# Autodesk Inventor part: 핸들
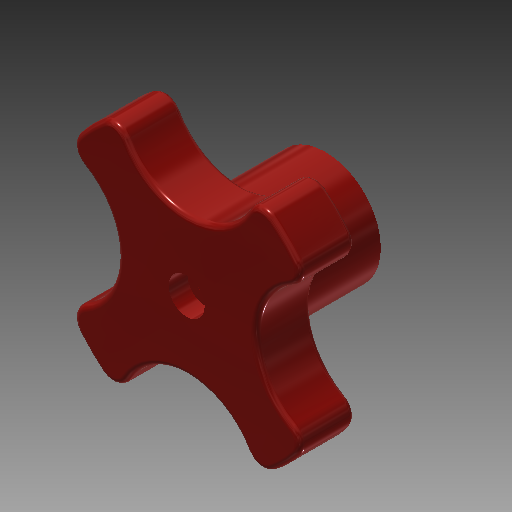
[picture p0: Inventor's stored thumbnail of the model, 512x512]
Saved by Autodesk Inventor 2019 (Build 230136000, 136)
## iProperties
Created: 2018-01
Part Number: 핸들
Material: ABS 플라스틱
Document SubType Name: Modeling
Designer: mduedu
Density: 1 g/cm^3
Appearance: 주황색-빨간색
Author: mduedu
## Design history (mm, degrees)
sketch "스케치1"
  geometry: C1 r 10 at (0, 0); C2 r 25 at (0, 0); 1 further point
  constraints: 2 centre point, 2 coincident
  dimensions: "d0" = 20 diameter of C1; "d1" = 50 diameter of C2
extrude "돌출1" new body sketch "스케치1" distance "d2" = 15; taper "d3" = 0 deg
extrude "돌출2" join sketch "스케치1" distance "d4" = 10; taper "d5" = 0 deg
sketch "스케치2" dims "d8" = 15
  geometry: L1 (-6, -6)-(-4.5, -6); L2 (6, -6)-(6, -4.5); L3 (6, 6)-(4.5, 6); L4 (-6, 6)-(-6, 4.5); L5 (-6, -6)-(6, 6); L6 (6, -6)-(-6, 6); L7 (-4.5, 6)-(-6, 6); L8 (4.5, 6)-(-4.5, 6); L9 (6, 4.5)-(6, 6); L10 (6, -4.5)-(6, 4.5); L11 (4.5, -6)-(6, -6); L12 (-4.5, -6)-(4.5, -6); L13 (-6, -4.5)-(-6, -6); L14 (-6, 4.5)-(-6, -4.5); 2 further points
  constraints: 28 end point, 18 parallel, 9 perpendicular, 3 horizontal, 2 midpoint, 1 coincident, 10 other
  dimensions: "d6" = 12 distance of L4.start L3.start; "d7" = 12 distance of L3.start L2.start
extrude "돌출3" cut sketch "스케치2" distance "d9" = 15; taper "d10" = 0 deg
sketch "스케치3"
  geometry: C1 r 12.5 at (25, 0); 2 further points
  constraints: 2 horizontal alignment, 1 centre point, 1 other
  dimensions: "d14" = 25 diameter of C1
extrude "돌출4" cut sketch "스케치3" extent not by distance; stored distance "d15" = 15; taper "d16" = 0 deg
fillet "모깎기1" dims "d20" = 3
fillet "모깎기2" dims "d24" = 1
sketch "스케치4"
  geometry: 2 further points
  constraints: 1 coincident
sketch "스케치5"
  geometry: 2 further points
  constraints: 1 coincident
hole "구멍1" sketch "스케치5" at (0, 0) diameter "d25" = 3.4; stored, may be unused: countersink angle "d29" = 90 deg, drill point angle "d31" = 0 deg; dims "d26" = 6, "d27" = 6.5, "d28" = 3.4, "d30" = 8
node "솔리드1"
pattern_circular "원형 패턴1" dims angle "d18" = 360 deg
pattern_circular "원형 패턴2" dims angle "d22" = 360 deg
node "투영된 루프1"
